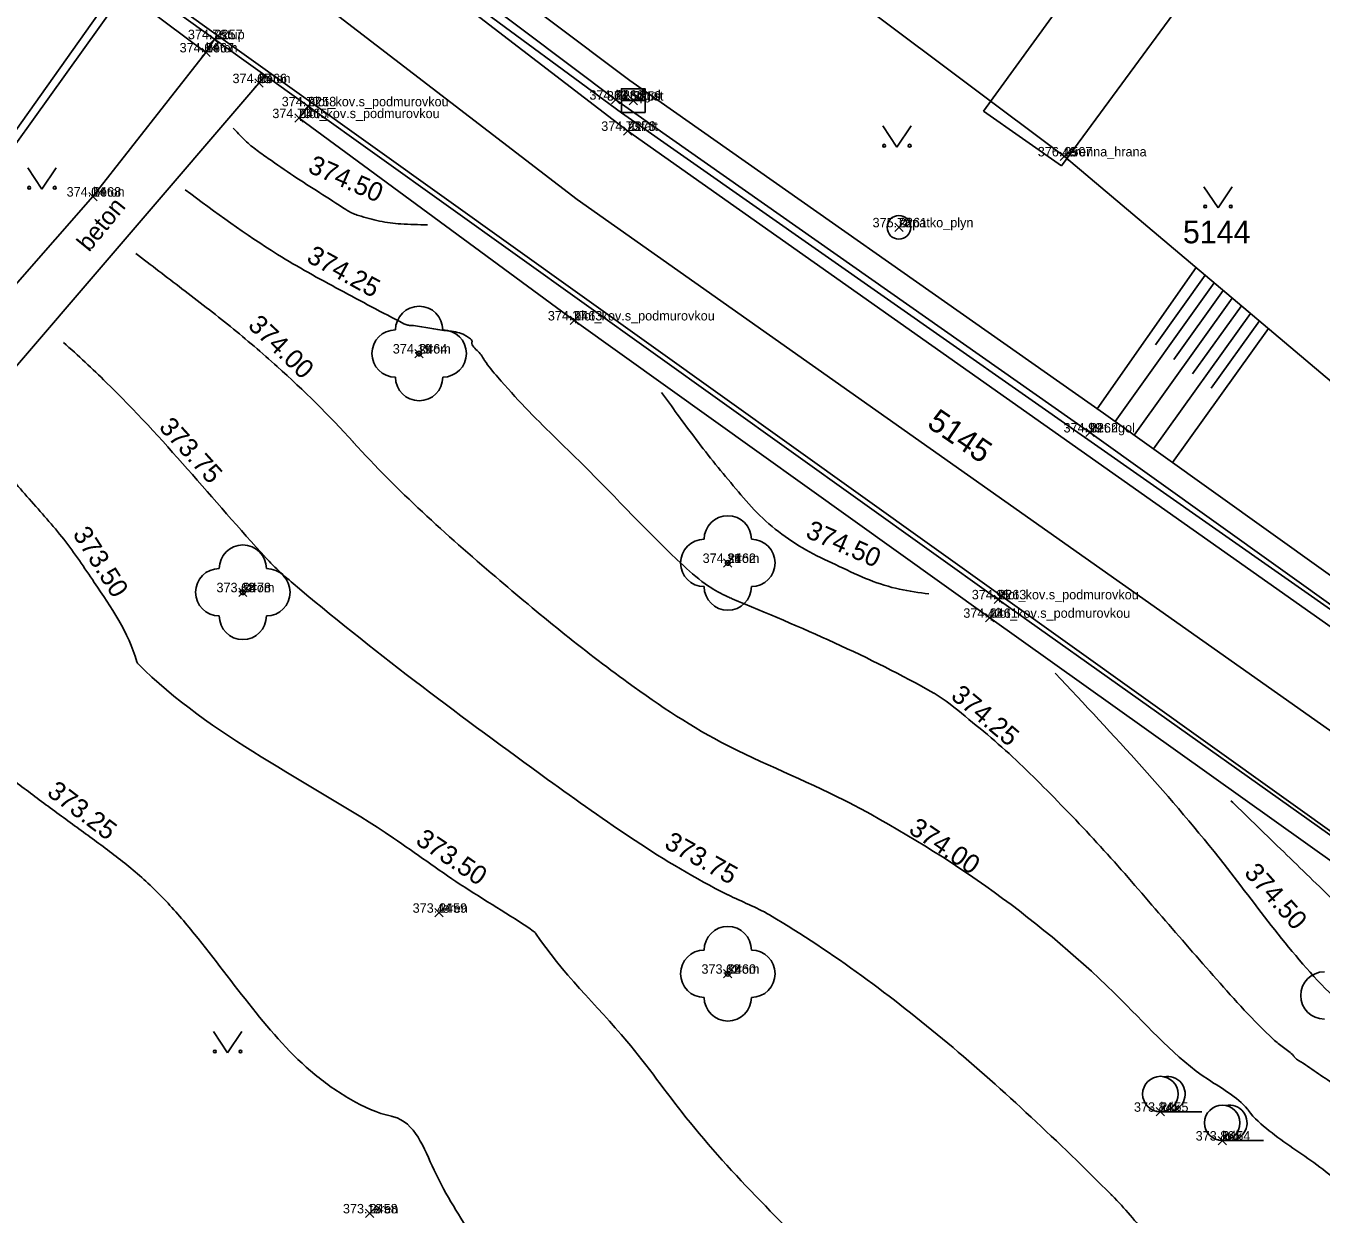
# Model space of a CAD drawing. Extents: x -400488 to -400124, y -1251493 to -1251223.
# Drawn here: x -400310.33 to -400282.93, y -1251353.83 to -1251328.7 of the extents above; entities that cross this region are included whole.
import ezdxf

# ---------------------------------------------------------------- set-up
doc = ezdxf.new("R2010")
doc.units = 0
for name, color, linetype in [('Level 20', 7, 'Continuous'), ('Level 21', 7, 'Continuous'), ('Level 22', 7, 'Continuous'), ('Level 23', 7, 'Continuous'), ('Level 31', 7, 'Continuous'), ('Level 32', 7, 'Continuous'), ('Level 34', 7, 'Continuous'), ('Level 35', 7, 'Continuous'), ('Level 36', 7, 'Continuous'), ('Level 49', 7, 'Continuous'), ('Level 50', 7, 'Continuous'), ('Level 52', 7, 'Continuous'), ('Level 63', 7, 'Continuous')]:
    doc.layers.add(name, color=color, linetype=linetype)

msp = doc.modelspace()

# ---------------------------------------------------------------- linework, layer by layer
at = {"layer": 'Level 20'}
for p, q in [((-400306.428, -1251329.068), (-400306.252, -1251328.892)), ((-400306.252, -1251329.068), (-400306.428, -1251328.892)), ((-400306.608, -1251329.348), (-400306.432, -1251329.172)), ((-400306.432, -1251329.348), (-400306.608, -1251329.172)), ((-400305.488, -1251329.998), (-400305.312, -1251329.822)), ((-400305.312, -1251329.998), (-400305.488, -1251329.822)), ((-400297.938, -1251330.348), (-400297.762, -1251330.172)), ((-400297.762, -1251330.348), (-400297.938, -1251330.172)), ((-400297.568, -1251330.368), (-400297.392, -1251330.192)), ((-400297.392, -1251330.368), (-400297.568, -1251330.192)), ((-400304.448, -1251330.488), (-400304.272, -1251330.312)), ((-400304.272, -1251330.488), (-400304.448, -1251330.312)), ((-400304.638, -1251330.738), (-400304.462, -1251330.562)), ((-400304.462, -1251330.738), (-400304.638, -1251330.562)), ((-400297.688, -1251331.008), (-400297.512, -1251330.832)), ((-400297.512, -1251331.008), (-400297.688, -1251330.832)), ((-400288.448, -1251331.548), (-400288.272, -1251331.372)), ((-400288.272, -1251331.548), (-400288.448, -1251331.372)), ((-400308.998, -1251332.398), (-400308.822, -1251332.222)), ((-400308.822, -1251332.398), (-400308.998, -1251332.222)), ((-400291.948, -1251333.048), (-400291.772, -1251332.872)), ((-400291.772, -1251333.048), (-400291.948, -1251332.872)), ((-400298.818, -1251335.018), (-400298.642, -1251334.842)), ((-400298.642, -1251335.018), (-400298.818, -1251334.842)), ((-400302.098, -1251335.718), (-400301.922, -1251335.542)), ((-400301.922, -1251335.718), (-400302.098, -1251335.542)), ((-400287.908, -1251337.388), (-400287.732, -1251337.212)), ((-400287.732, -1251337.388), (-400287.908, -1251337.212)), ((-400295.568, -1251340.148), (-400295.392, -1251339.972)), ((-400295.392, -1251340.148), (-400295.568, -1251339.972)), ((-400305.828, -1251340.768), (-400305.652, -1251340.592)), ((-400305.652, -1251340.768), (-400305.828, -1251340.592)), ((-400289.848, -1251340.918), (-400289.672, -1251340.742)), ((-400289.672, -1251340.918), (-400289.848, -1251340.742)), ((-400290.028, -1251341.308), (-400289.852, -1251341.132)), ((-400289.852, -1251341.308), (-400290.028, -1251341.132)), ((-400301.678, -1251347.548), (-400301.502, -1251347.372)), ((-400301.502, -1251347.548), (-400301.678, -1251347.372)), ((-400295.568, -1251348.838), (-400295.392, -1251348.662)), ((-400295.392, -1251348.838), (-400295.568, -1251348.662)), ((-400286.418, -1251351.758), (-400286.242, -1251351.582)), ((-400286.242, -1251351.758), (-400286.418, -1251351.582)), ((-400285.108, -1251352.368), (-400284.932, -1251352.192)), ((-400284.932, -1251352.368), (-400285.108, -1251352.192)), ((-400303.148, -1251353.908), (-400302.972, -1251353.732)), ((-400302.972, -1251353.908), (-400303.148, -1251353.732))]:
    msp.add_line(p, q, dxfattribs=at)
at = {"layer": 'Level 31'}
for p, q in [((-400285.572, -1251333.813), (-400287.666, -1251336.797)), ((-400285.381, -1251333.974), (-400286.435, -1251335.448)), ((-400285.19, -1251334.135), (-400287.286, -1251337.067)), ((-400284.998, -1251334.296), (-400286.041, -1251335.754)), ((-400284.807, -1251334.458), (-400286.881, -1251337.357)), ((-400284.425, -1251334.78), (-400286.475, -1251337.647)), ((-400284.616, -1251334.619), (-400285.647, -1251336.06)), ((-400284.043, -1251335.102), (-400286.07, -1251337.937)), ((-400284.234, -1251334.941), (-400285.253, -1251336.366))]:
    msp.add_line(p, q, dxfattribs=at)
for points in [[(-400318.26, -1251315.35), (-400312.96, -1251313.03), (-400288.36, -1251331.46), (-400266.982, -1251349.498)], [(-400316.14, -1251315.89), (-400316.44, -1251316.29), (-400297.85, -1251330.26), (-400287.82, -1251337.3), (-400269.11, -1251350.68), (-400268.97, -1251350.75), (-400268.595, -1251350.721), (-400268.22, -1251350.66), (-400265.46, -1251349.31), (-400264.73, -1251348.69)], [(-400316.14, -1251315.89), (-400297.556, -1251329.855), (-400287.531, -1251336.892), (-400268.865, -1251350.24), (-400268.655, -1251350.224), (-400268.373, -1251350.178), (-400265.736, -1251348.888), (-400265.364, -1251348.599), (-400265.054, -1251348.309), (-400262.095, -1251344.059)], [(-400306.52, -1251329.26), (-400308.91, -1251332.31), (-400311.36, -1251335.09), (-400313.14, -1251336.64), (-400315.1, -1251337.87), (-400315.32, -1251337.75)], [(-400305.274, -1251329.745), (-400305.4, -1251329.91), (-400311.02, -1251336.46), (-400315.51, -1251340.11), (-400320.25, -1251346.65), (-400324.05, -1251351.79)]]:
    msp.add_lwpolyline(points, dxfattribs=at)
at = {"layer": 'Level 32'}
for points in [[(-400312.5, -1251319.48), (-400297.6, -1251330.92), (-400269.6, -1251350.67), (-400269.57, -1251350.69), (-400268.48, -1251351.39), (-400267.759, -1251351.812), (-400266.88, -1251352.23), (-400265.72, -1251352.64), (-400264.993, -1251352.795), (-400264.19, -1251352.85), (-400263.653, -1251352.732), (-400263.2, -1251352.53), (-400262.601, -1251352.1), (-400262.03, -1251351.63), (-400261.48, -1251350.91)], [(-400313.317, -1251321.122), (-400298.667, -1251332.37), (-400270.618, -1251352.155), (-400270.556, -1251352.196), (-400267.742, -1251354.003)]]:
    msp.add_lwpolyline(points, dxfattribs=at)
at = {"layer": 'Level 34'}
msp.add_lwpolyline([(-400318.045, -1251327.281), (-400314.71, -1251322.56), (-400307.87, -1251327.43), (-400308.07, -1251327.73), (-400312.65, -1251334.13)], dxfattribs=at)
at = {"layer": 'Level 35'}
for points in [[(-400308.07, -1251327.73), (-400306.34, -1251328.98)], [(-400308.245, -1251327.974), (-400306.52, -1251329.26), (-400306.34, -1251328.98)], [(-400306.34, -1251328.98), (-400304.36, -1251330.4)], [(-400271.73, -1251354.05), (-400280.61, -1251347.87), (-400289.94, -1251341.22), (-400298.73, -1251334.93), (-400304.55, -1251330.65), (-400304.36, -1251330.4)], [(-400304.36, -1251330.4), (-400289.76, -1251340.83), (-400270.68, -1251354.37)]]:
    msp.add_lwpolyline(points, dxfattribs=at)
at = {"layer": 'Level 36'}
for p, q in [((-400291.903, -1251331.263), (-400292.203, -1251330.813)), ((-400291.903, -1251331.263), (-400291.603, -1251330.813)), ((-400309.99, -1251332.152), (-400310.29, -1251331.702)), ((-400309.99, -1251332.152), (-400309.69, -1251331.702)), ((-400306.061, -1251350.425), (-400306.361, -1251349.975)), ((-400306.061, -1251350.425), (-400305.761, -1251349.975)), ((-400286.33, -1251351.67), (-400285.455, -1251351.67)), ((-400285.02, -1251352.28), (-400284.145, -1251352.28))]:
    msp.add_line(p, q, dxfattribs=at)
for centre, radius in [((-400292.173, -1251331.233), 0.03), ((-400291.633, -1251331.233), 0.03), ((-400310.26, -1251332.122), 0.03), ((-400309.72, -1251332.122), 0.03), ((-400302.01, -1251335.63), 0.05), ((-400295.48, -1251340.06), 0.05), ((-400305.74, -1251340.68), 0.05), ((-400295.48, -1251348.75), 0.05), ((-400306.331, -1251350.395), 0.03), ((-400305.791, -1251350.395), 0.03), ((-400286.33, -1251351.295), 0.375), ((-400285.02, -1251351.905), 0.375)]:
    msp.add_circle(centre, radius, dxfattribs=at)
for centre, radius, start, end in [((-400302.01, -1251335.13), 0.5, 0, 180), ((-400302.51, -1251335.63), 0.5, 90, 270), ((-400301.51, -1251335.63), 0.5, 270, 90), ((-400302.01, -1251336.13), 0.5, 180, 0), ((-400295.48, -1251339.56), 0.5, 0, 180), ((-400305.74, -1251340.18), 0.5, 0, 180), ((-400295.98, -1251340.06), 0.5, 90, 270), ((-400294.98, -1251340.06), 0.5, 270, 90), ((-400306.24, -1251340.68), 0.5, 90, 270), ((-400305.24, -1251340.68), 0.5, 270, 90), ((-400295.48, -1251340.56), 0.5, 180, 0), ((-400305.74, -1251341.18), 0.5, 180, 0), ((-400295.48, -1251348.25), 0.5, 0, 180), ((-400295.98, -1251348.75), 0.5, 90, 270), ((-400294.98, -1251348.75), 0.5, 270, 90), ((-400282.86, -1251349.21), 0.5, 90, 270), ((-400295.48, -1251349.25), 0.5, 180, 0), ((-400286.18, -1251351.295), 0.375, 270, 101.537), ((-400284.87, -1251351.905), 0.375, 270, 101.537)]:
    msp.add_arc(centre, radius, start, end, dxfattribs=at)
at = {"layer": 'Level 49'}
for points in [[(-400301.83, -1251332.91), (-400302.396, -1251332.887), (-400302.622, -1251332.866), (-400302.847, -1251332.827), (-400303.069, -1251332.774), (-400303.291, -1251332.71), (-400303.521, -1251332.611), (-400303.564, -1251332.583), (-400304.665, -1251331.873), (-400305.204, -1251331.502), (-400305.471, -1251331.31), (-400305.599, -1251331.207), (-400305.72, -1251331.096), (-400305.944, -1251330.86)], [(-400278.631, -1251370.004), (-400278.118, -1251366.954), (-400277.412, -1251363.928), (-400277.404, -1251363.9), (-400277.243, -1251363.447), (-400277.063, -1251363.002), (-400276.883, -1251362.554), (-400276.725, -1251362.096), (-400276.548, -1251361.022), (-400276.561, -1251359.49), (-400276.508, -1251355.66), (-400276.495, -1251355.542), (-400276.499, -1251355.304), (-400276.5, -1251355.302), (-400276.561, -1251355.147), (-400276.562, -1251355.145), (-400276.659, -1251355.037), (-400276.991, -1251354.829), (-400277.106, -1251354.817), (-400277.114, -1251354.814), (-400277.554, -1251354.518), (-400280.527, -1251352.524), (-400282.011, -1251351.524), (-400282.752, -1251351.021), (-400283.123, -1251350.771), (-400283.308, -1251350.645), (-400283.491, -1251350.515), (-400283.5, -1251350.503), (-400283.513, -1251350.487), (-400283.613, -1251350.393), (-400283.723, -1251350.31), (-400283.834, -1251350.228), (-400283.937, -1251350.138), (-400285.14, -1251348.868), (-400286.294, -1251347.546), (-400287.449, -1251346.222), (-400288.656, -1251344.945), (-400289.834, -1251343.824), (-400290.459, -1251343.304), (-400291.116, -1251342.818), (-400291.123, -1251342.814), (-400295.387, -1251340.816), (-400295.481, -1251340.776), (-400295.888, -1251340.55), (-400296.417, -1251340.117), (-400298.55, -1251337.977), (-400299.765, -1251336.773), (-400300.345, -1251336.13), (-400300.624, -1251335.775), (-400300.759, -1251335.587), (-400300.892, -1251335.391), (-400300.889, -1251335.373), (-400300.892, -1251335.36), (-400300.967, -1251335.291), (-400301.043, -1251335.241), (-400301.201, -1251335.182), (-400301.531, -1251335.135), (-400302.215, -1251335.034), (-400302.251, -1251335.031), (-400302.332, -1251334.999), (-400303.687, -1251334.283), (-400305.005, -1251333.533), (-400306.96, -1251332.166)], [(-400282.087, -1251375.169), (-400281.69, -1251370.822), (-400281.381, -1251368.586), (-400280.551, -1251363.9), (-400280.546, -1251363.886), (-400280.15, -1251362.887), (-400279.737, -1251361.896), (-400279.326, -1251360.9), (-400278.941, -1251359.886), (-400278.883, -1251359.562), (-400278.885, -1251359.094), (-400279.241, -1251356.971), (-400279.631, -1251356.354), (-400280.512, -1251355.223), (-400282.534, -1251353.186), (-400283.018, -1251352.792), (-400283.53, -1251352.437), (-400284.027, -1251352.07), (-400284.466, -1251351.641), (-400284.483, -1251351.618), (-400284.488, -1251351.612), (-400285.314, -1251350.99), (-400287.151, -1251349.31), (-400292.845, -1251345.168), (-400292.862, -1251345.159), (-400295.431, -1251343.95), (-400295.488, -1251343.921), (-400297.591, -1251342.594), (-400300.391, -1251340.357), (-400303.398, -1251337.509), (-400303.407, -1251337.499), (-400305.011, -1251335.906), (-400306.002, -1251335.061), (-400307.028, -1251334.259), (-400308.006, -1251333.512)], [(-400287.056, -1251382.036), (-400285.095, -1251371.378), (-400283.83, -1251364.736), (-400283.748, -1251364.223), (-400283.689, -1251363.872), (-400283.457, -1251363.276), (-400283.446, -1251363.218), (-400283.447, -1251363.211), (-400283.984, -1251359.342), (-400286.608, -1251354.299), (-400287.35, -1251353.443), (-400287.372, -1251353.421), (-400290.829, -1251350.218), (-400294.574, -1251347.519), (-400294.601, -1251347.503), (-400295.474, -1251347.083), (-400295.494, -1251347.073), (-400299.293, -1251344.638), (-400304.542, -1251340.608), (-400305.224, -1251339.982), (-400305.246, -1251339.958), (-400308.629, -1251336.24), (-400309.532, -1251335.395)], [(-400291.23, -1251340.714), (-400291.85, -1251340.615), (-400292.483, -1251340.42), (-400293.121, -1251340.133), (-400293.751, -1251339.826), (-400294.864, -1251338.994), (-400295.311, -1251338.49), (-400295.739, -1251337.974), (-400296.549, -1251336.911), (-400296.88, -1251336.453)], [(-400298.594, -1251390.918), (-400297.579, -1251389.803), (-400296.576, -1251388.675), (-400295.294, -1251386.973), (-400294.717, -1251386.031), (-400294.176, -1251385.068), (-400293.64, -1251384.103), (-400293.079, -1251383.154), (-400292.558, -1251382.354), (-400292.017, -1251381.567), (-400291.474, -1251380.779), (-400290.946, -1251379.978), (-400290.936, -1251379.958), (-400290.353, -1251377.108), (-400290.345, -1251377.073), (-400289.148, -1251371.673), (-400289.131, -1251371.633), (-400288.68, -1251369.757), (-400288.682, -1251369.751), (-400289.179, -1251365.184), (-400289.187, -1251365.045), (-400289.199, -1251364.086), (-400289.178, -1251363.127), (-400289.151, -1251362.167), (-400289.146, -1251361.208), (-400289.326, -1251359.947), (-400289.998, -1251358.61), (-400290.194, -1251358.383), (-400290.2, -1251358.378), (-400291.608, -1251356.855), (-400292.307, -1251356.088), (-400293.021, -1251355.336), (-400293.116, -1251355.24), (-400296.365, -1251351.788), (-400297.616, -1251350.178), (-400299.549, -1251347.891), (-400299.559, -1251347.877), (-400299.595, -1251347.847), (-400301.142, -1251346.859), (-400302.556, -1251345.879), (-400307.962, -1251342.189), (-400307.971, -1251342.179), (-400307.982, -1251342.152), (-400308.883, -1251340.471), (-400309.528, -1251339.56), (-400310.26, -1251338.706), (-400310.968, -1251337.837), (-400311.406, -1251337.164)], [(-400300.667, -1251389.478), (-400300.483, -1251388.773), (-400300.384, -1251388.062), (-400300.344, -1251387.35), (-400300.339, -1251386.641), (-400300.34, -1251386.636), (-400300.362, -1251386.605), (-400300.534, -1251386.354), (-400300.515, -1251385.99), (-400300.109, -1251385.615), (-400297.14, -1251382.932), (-400297.057, -1251382.855), (-400295.589, -1251381.52), (-400295.422, -1251381.289), (-400295.284, -1251381.059), (-400295.265, -1251381.015), (-400294.968, -1251379.948), (-400294.642, -1251379.013), (-400294.274, -1251378.09), (-400293.924, -1251377.161), (-400293.647, -1251376.207), (-400293.646, -1251376.19), (-400293.641, -1251376.158), (-400292.799, -1251374.602), (-400292.78, -1251374.568), (-400292.201, -1251371.517), (-400292.573, -1251371.086), (-400292.863, -1251370.616), (-400292.873, -1251370.59), (-400293.119, -1251369.55), (-400293.291, -1251368.49), (-400293.49, -1251367.439), (-400293.821, -1251366.425), (-400295.335, -1251363.46), (-400297.084, -1251360.63), (-400298.379, -1251358.699), (-400299.238, -1251357.272), (-400300.054, -1251355.818), (-400300.862, -1251354.357), (-400301.693, -1251352.905), (-400302.556, -1251351.775), (-400302.586, -1251351.768), (-400302.595, -1251351.766), (-400303.457, -1251351.41), (-400304.217, -1251350.882), (-400305.536, -1251349.48), (-400306.763, -1251347.91), (-400307.407, -1251347.171), (-400308.106, -1251346.519), (-400308.834, -1251345.958), (-400309.579, -1251345.414), (-400310.323, -1251344.863), (-400311.049, -1251344.285), (-400311.07, -1251344.262), (-400311.075, -1251344.251), (-400312.804, -1251340.258), (-400313.009, -1251339.843), (-400313.235, -1251339.439), (-400313.463, -1251339.034), (-400313.486, -1251338.992)], [(-400274.109, -1251364.042), (-400274.008, -1251363.383), (-400273.954, -1251363.053), (-400273.943, -1251362.724), (-400273.958, -1251362.626), (-400273.997, -1251362.507), (-400274.011, -1251362.47), (-400274.012, -1251362.468), (-400274.162, -1251361.825), (-400274.25, -1251361.177), (-400274.313, -1251359.872), (-400274.338, -1251357.988), (-400274.341, -1251357.92), (-400274.598, -1251355.942), (-400274.603, -1251355.924), (-400275.052, -1251354.804), (-400275.058, -1251354.792), (-400275.759, -1251354.005), (-400278.319, -1251352.191), (-400278.397, -1251352.171), (-400278.453, -1251352.154), (-400281.685, -1251349.955), (-400282.516, -1251349.39), (-400282.517, -1251349.388), (-400282.537, -1251349.359), (-400282.59, -1251349.305), (-400284.983, -1251346.43), (-400288.552, -1251342.393)], [(-400298.007, -1251373.633), (-400298.101, -1251373.657), (-400298.385, -1251373.715), (-400298.668, -1251373.698), (-400298.999, -1251373.598), (-400299.315, -1251373.468), (-400299.9, -1251373.106), (-400300.929, -1251372.15), (-400302.098, -1251370.777), (-400305.291, -1251366.626), (-400307.213, -1251363.775), (-400309.026, -1251360.802), (-400309.479, -1251359.989), (-400309.683, -1251359.57), (-400309.864, -1251359.138), (-400309.872, -1251359.107), (-400310.092, -1251357.753), (-400310.245, -1251356.389), (-400310.408, -1251355.025), (-400310.657, -1251353.672), (-400310.667, -1251353.649), (-400314.159, -1251348.989), (-400316.285, -1251346.155), (-400316.296, -1251346.134), (-400316.569, -1251345.318), (-400316.732, -1251344.464), (-400316.96, -1251343.625)], [(-400271.965, -1251360.814), (-400272.009, -1251360.689), (-400272.186, -1251360.237), (-400272.197, -1251360.198), (-400272.225, -1251359.97), (-400272.697, -1251356.579), (-400272.706, -1251356.547), (-400273.542, -1251354.461), (-400273.554, -1251354.438), (-400273.691, -1251354.234), (-400273.837, -1251354.037), (-400274.155, -1251353.667), (-400274.498, -1251353.316), (-400274.859, -1251352.974), (-400275.963, -1251351.93), (-400277.098, -1251350.932), (-400277.684, -1251350.485), (-400277.992, -1251350.283), (-400278.313, -1251350.095), (-400278.97, -1251349.772), (-400279.657, -1251349.533), (-400279.687, -1251349.525), (-400279.791, -1251349.497), (-400280.227, -1251349.321), (-400280.628, -1251349.067), (-400281.363, -1251348.446), (-400281.375, -1251348.435), (-400282.483, -1251347.375), (-400283.583, -1251346.308), (-400284.682, -1251345.24), (-400284.836, -1251345.091)]]:
    msp.add_spline(points, degree=3, dxfattribs=at)
at = {"layer": 'Level 50'}
msp.add_circle((-400291.86, -1251332.96), 0.25, dxfattribs=at)
at = {"layer": 'Level 52'}
msp.add_lwpolyline([(-400297.73, -1251330.28), (-400297.73, -1251330.03), (-400297.23, -1251330.03), (-400297.23, -1251330.28)], dxfattribs=at)
msp.add_lwpolyline([(-400297.73, -1251330.28), (-400297.23, -1251330.28), (-400297.23, -1251330.53), (-400297.73, -1251330.53)], close=True, dxfattribs=at)
at = {"layer": 'Level 63'}
for p, q in [((-400297.73, -1251330.54), (-400318.35, -1251315.34)), ((-400318.35, -1251315.34), (-400297.73, -1251330.54)), ((-400290.07, -1251330.5), (-400280.04, -1251316.67)), ((-400278.27, -1251317.84), (-400288.42, -1251331.66)), ((-400312.75, -1251334.01), (-400308.16, -1251327.55)), ((-400308.16, -1251327.55), (-400312.75, -1251334.01)), ((-400308.16, -1251327.55), (-400270.88, -1251354.21)), ((-400270.88, -1251354.21), (-400308.16, -1251327.55)), ((-400265.38, -1251353.2), (-400297.73, -1251330.54)), ((-400297.73, -1251330.54), (-400265.38, -1251353.2)), ((-400288.42, -1251331.66), (-400290.07, -1251330.5)), ((-400285.41, -1251332.1), (-400285.11, -1251332.55)), ((-400285.11, -1251332.55), (-400284.81, -1251332.1))]:
    msp.add_line(p, q, dxfattribs=at)
for centre in [(-400285.38, -1251332.52), (-400284.84, -1251332.52)]:
    msp.add_circle(centre, 0.03, dxfattribs=at)

# ---------------------------------------------------------------- texts
at = {"layer": 'Level 21'}
for s, p in [('2257', (-400306.34, -1251328.98)), ('2467', (-400306.52, -1251329.26)), ('2466', (-400305.4, -1251329.91)), ('2258', (-400304.36, -1251330.4)), ('2260', (-400297.85, -1251330.26)), ('2259', (-400297.48, -1251330.28)), ('2465', (-400304.55, -1251330.65)), ('2273', (-400297.6, -1251330.92)), ('2507', (-400288.36, -1251331.46)), ('2468', (-400308.91, -1251332.31)), ('2261', (-400291.86, -1251332.96)), ('2463', (-400298.73, -1251334.93)), ('2464', (-400302.01, -1251335.63)), ('2262', (-400287.82, -1251337.3)), ('2462', (-400295.48, -1251340.06)), ('2478', (-400305.74, -1251340.68)), ('2263', (-400289.76, -1251340.83)), ('2461', (-400289.94, -1251341.22)), ('2459', (-400301.59, -1251347.46)), ('2460', (-400295.48, -1251348.75)), ('2455', (-400286.33, -1251351.67)), ('2454', (-400285.02, -1251352.28)), ('2458', (-400303.06, -1251353.82))]:
    msp.add_text(s, height=0.2, dxfattribs=at).set_placement(p)
at = {"layer": 'Level 22'}
for s, p in [('vstup', (-400306.34, -1251328.98)), ('beton', (-400306.52, -1251329.26)), ('beton', (-400305.4, -1251329.91)), ('plot_kov.s_podmurovkou', (-400304.36, -1251330.4)), ('bet.rigol', (-400297.85, -1251330.26)), ('vpust', (-400297.48, -1251330.28)), ('plot_kov.s_podmurovkou', (-400304.55, -1251330.65)), ('asfalt', (-400297.6, -1251330.92)), ('terenna_hrana', (-400288.36, -1251331.46)), ('beton', (-400308.91, -1251332.31)), ('supatko_plyn', (-400291.86, -1251332.96)), ('plot_kov.s_podmurovkou', (-400298.73, -1251334.93)), ('strom', (-400302.01, -1251335.63)), ('bet.rigol', (-400287.82, -1251337.3)), ('strom', (-400295.48, -1251340.06)), ('strom', (-400305.74, -1251340.68)), ('plot_kov.s_podmurovkou', (-400289.76, -1251340.83)), ('plot_kov.s_podmurovkou', (-400289.94, -1251341.22)), ('teren', (-400301.59, -1251347.46)), ('strom', (-400295.48, -1251348.75)), ('krik', (-400286.33, -1251351.67)), ('krik', (-400285.02, -1251352.28)), ('teren', (-400303.06, -1251353.82))]:
    msp.add_text(s, height=0.2, dxfattribs=at).set_placement(p)
at = {"layer": 'Level 23'}
for s, p in [('374.76', (-400306.903, -1251328.98)), ('374.64', (-400307.078, -1251329.26)), ('374.65', (-400305.959, -1251329.91)), ('374.77', (-400304.918, -1251330.4)), ('374.63', (-400298.408, -1251330.26)), ('374.58', (-400298.038, -1251330.28)), ('374.70', (-400305.116, -1251330.65)), ('374.73', (-400298.158, -1251330.92)), ('376.46', (-400288.923, -1251331.46)), ('374.04', (-400309.468, -1251332.31)), ('375.78', (-400292.418, -1251332.96)), ('374.37', (-400299.288, -1251334.93)), ('374.19', (-400302.568, -1251335.63)), ('374.99', (-400288.378, -1251337.3)), ('374.31', (-400296.013, -1251340.06)), ('373.68', (-400306.298, -1251340.68)), ('374.95', (-400290.319, -1251340.83)), ('374.42', (-400290.498, -1251341.22)), ('373.44', (-400302.148, -1251347.46)), ('373.62', (-400296.038, -1251348.75)), ('373.84', (-400286.888, -1251351.67)), ('373.86', (-400285.583, -1251352.28)), ('373.16', (-400303.623, -1251353.82))]:
    msp.add_text(s, height=0.2, dxfattribs=at).set_placement(p)
at = {"layer": 'Level 31'}
msp.add_text('beton', height=0.375, rotation=50.7936, dxfattribs=at).set_placement((-400308.993, -1251333.499))
at = {"layer": 'Level 49'}
for s, rotation, p in [('374.50', 336.3303, (-400304.385, -1251331.786)), ('374.25', 331.265, (-400304.416, -1251333.674)), ('374.00', 316.0204, (-400305.653, -1251335.06)), ('373.75', 312.3027, (-400307.534, -1251337.203)), ('374.50', 336.3635, (-400293.856, -1251339.51)), ('373.50', 302.3754, (-400309.351, -1251339.448)), ('374.25', 320.0631, (-400290.785, -1251342.911)), ('373.25', 322.8474, (-400309.906, -1251344.958)), ('374.00', 326.0381, (-400291.679, -1251345.754)), ('373.50', 326.0672, (-400302.108, -1251345.988)), ('373.75', 330.6058, (-400296.848, -1251346.072)), ('374.50', 311.5186, (-400284.575, -1251346.628))]:
    msp.add_text(s, height=0.4, rotation=rotation, dxfattribs=at).set_placement(p)
at = {"layer": 'Level 63'}
msp.add_text('5144', height=0.48, dxfattribs=at).set_placement((-400285.852, -1251333.298))
msp.add_text('5145', height=0.48, rotation=325.8735, dxfattribs=at).set_placement((-400291.29, -1251337.169))

doc.saveas('drawing.dxf')
